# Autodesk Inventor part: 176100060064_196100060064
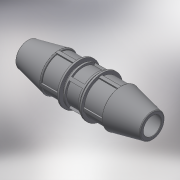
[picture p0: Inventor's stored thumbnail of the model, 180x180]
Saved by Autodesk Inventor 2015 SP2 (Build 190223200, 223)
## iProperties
Created: 2016-12
Part Number: 176100060064_196100060064
Material: Generic
Description: PLASSON UNIVERSAL SLIP REPAIR COUPLER 60-64 SERIES 17
Document SubType Name: Modeling
Designer: KIM
Mass: 305.707 g
Surface Area: 640.661 cm^2
Volume: 305.707 cm^3
Density: 1 g/cm^3
Appearance: Default
Author: KIM
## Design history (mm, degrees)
derived "17610.ipt"
feature "Solid1::17610.ipt"
tag "TaggingFeature1"
body "Solid1"
other parameters: "d5" = 176, "d11" = 44, "d12" = 3.52, "d13" = 89.6, "d14" = 77.5, "d15" = 64, "d16" = 62.72, "d17" = 96, "d20" = 102, "d21" = 80 deg, "d22" = 44.28571, "d23" = 0, "d25" = 360 deg, "d31" = 35.2, "d32" = 108, "d33" = 80 deg, "d34" = 40 deg, "d35" = 96, "d36" = 14.08, "d37" = 0, "d39" = 360 deg, "d41" = 3.1, "d43" = 360 deg, "d48" = 3.2, "d52" = 1.2, "d56" = 110.4, "d_" = 64, "l_" = 176
